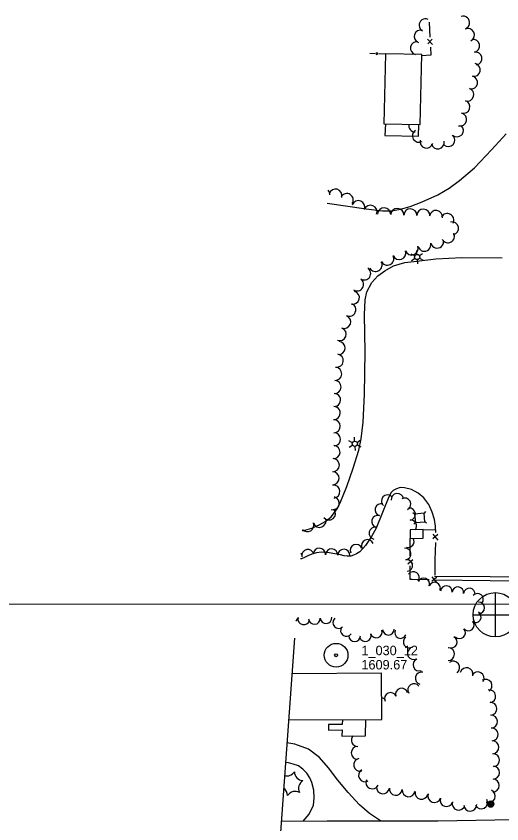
# Model space of a CAD drawing. Extents: x 189384 to 193282, y 256970 to 260388.
# Drawn here: x 190447 to 190754, y 259872 to 260383 of the extents above; entities that cross this region are included whole.
import ezdxf

# ---------------------------------------------------------------- set-up
doc = ezdxf.new("R2010")
doc.units = 0
for name, color, linetype in [('E_DWY', 7, 'Continuous'), ('E_LAND_Vegetation', 7, 'Continuous'), ('E_MAP_GridLines', 7, 'Continuous'), ('E_MAP_Limits', 7, 'Continuous'), ('E_MAP_PassPoints', 7, 'Continuous'), ('E_MISCPROP', 7, 'Continuous'), ('E_MISCPROP_HvyDash', 7, 'Continuous'), ('E_MISCPROP_HvyLine', 7, 'Continuous'), ('E_MISCPROP_Railing', 7, 'Continuous'), ('E_RDWY', 7, 'Continuous'), ('E_UTL_AboveGroundPipe', 7, 'Continuous')]:
    doc.layers.add(name, color=color, linetype=linetype)

# ---------------------------------------------------------------- blocks, each defined once
blk = doc.blocks.new('PP')
at = {"layer": 'E_MAP_PassPoints'}
for radius in [7.5, 0.96]:
    blk.add_circle((0, 0), radius, dxfattribs=at)
blk = doc.blocks.new('PHOTOC')
at = {"layer": 'E_MAP_Limits'}
for p, q in [((0.12, 14.06), (0.06, -13.8)), ((-13.79, 0.03), (14.12, 0.01))]:
    blk.add_line(p, q, dxfattribs=at)
blk.add_circle((0.17, 0.03), 14, dxfattribs=at)
blk = doc.blocks.new('POLE_1')
at = {"layer": 'E_MISCPROP'}
for radius in [2.02, 1.51, 1.01, 0.504]:
    blk.add_circle((0.03, -0.09), radius, dxfattribs=at)
blk = doc.blocks.new('PED')
at = {"layer": 'E_UTL_AboveGroundPipe'}
for p, q in [((-2.34, 2.71), (-3.29, 3.77)), ((3.06, 2.71), (4.02, 3.77)), ((-3.29, -4.35), (-2.34, -3.29)), ((4.02, -4.35), (3.06, -3.29))]:
    blk.add_line(p, q, dxfattribs=at)
blk.add_lwpolyline([(-2.34, -3.29), (3.06, -3.29), (3.06, 2.71), (-2.34, 2.71)], close=True, dxfattribs=at)
blk = doc.blocks.new('LTP')
at = {"layer": 'E_MISCPROP'}
for p, q in [((-1.61, 0.09), (-4.22, 0.17)), ((-0.78, 1.46), (-1.98, 3.76)), ((0.86, 1.37), (2.22, 3.6)), ((1.66, 0), (4.18, -0.06)), ((-0.86, -1.4), (-2.22, -3.59)), ((0.78, -1.44), (2.02, -3.62))]:
    blk.add_line(p, q, dxfattribs=at)
blk.add_circle((0.02, 0.01), 1.64, dxfattribs=at)

msp = doc.modelspace()

# ---------------------------------------------------------------- linework, layer by layer
at = {"layer": 'E_DWY'}
for points in [[(190643.16, 260264.92), (190667.89, 260261.27), (190678.21, 260260.12), (190683.78, 260260.16), (190689.54, 260261.1), (190695.61, 260262.79), (190703.32, 260265.85), (190713.11, 260270.21), (190720.22, 260274.32), (190726.8, 260279.31), (190736.3, 260287.29), (190746.97, 260298.59), (190756.41, 260308.77)], [(190627.59, 260057.72), (190633.42, 260059.47), (190638.58, 260061.64), (190642.3, 260063.74), (190645.66, 260066.61), (190649.08, 260071), (190651.49, 260075.37), (190655.58, 260085.72), (190659.68, 260097.44), (190663.3, 260108.83), (190664.72, 260115.93), (190665.9, 260126.36), (190666.8, 260144.09), (190667.19, 260171), (190666.82, 260194.34), (190667.22, 260203.75), (190668.32, 260208.94), (190671.46, 260214.83), (190675.26, 260219.05), (190679.6, 260222.23), (190685.18, 260225.38), (190692.26, 260227.29), (190699.93, 260228.32), (190711.79, 260229.61), (190728.33, 260230.48), (190753.84, 260230.25)], [(190711.73, 260058.38), (190711.64, 260060.68), (190711.1, 260064.98), (190709.66, 260069.51), (190707.39, 260074.47), (190704.29, 260078.62), (190700.73, 260081.63), (190696.51, 260083.88), (190692.13, 260084.98), (190689.38, 260085.07), (190687.06, 260084.28), (190684.98, 260083.25), (190683.75, 260082.04), (190682.18, 260079.32), (190674.24, 260059.34), (190671.19, 260054.11), (190667.38, 260048.37), (190663.85, 260044.39), (190661.64, 260043.17), (190659.83, 260042.34), (190658.07, 260041.73), (190655.9, 260041.74), (190653.92, 260041.91), (190651.61, 260042.49), (190644.37, 260043.75), (190639.61, 260044.24), (190636.46, 260043.72), (190634.19, 260043.13), (190631.39, 260042.07), (190629.25, 260040.99), (190626.93, 260040.11), (190626.25, 260039.94)], [(190711.08, 260026.64), (190746.18, 260026.36), (190775.97, 260026.01), (190799.66, 260025.72), (190848.64, 260026.04), (190882.45, 260024.72), (190913.98, 260024.45), (190936.58, 260024.1), (190955.27, 260023.64), (190967.58, 260022.95), (190981.47, 260021.68), (190988, 260020.82), (190991.83, 260019.97), (190995.29, 260017.95), (190997.01, 260015.5), (190998.22, 260011.96), (190998.94, 260008.09)], [(190711.1, 260029.14), (190746.2, 260028.86), (190776, 260028.51), (190799.66, 260028.22), (190848.68, 260028.54), (190882.51, 260027.22), (190914.01, 260026.95), (190936.63, 260026.6), (190955.37, 260026.14), (190967.76, 260025.44), (190981.75, 260024.16), (190988.44, 260023.29), (190992.75, 260022.33), (190997.03, 260019.84), (190999.26, 260016.65), (191000.65, 260012.6), (191001.4, 260008.55)], [(190677, 259874.33), (190669.93, 259878.96), (190663.6, 259884.48), (190656.41, 259892.24), (190649.97, 259900.15), (190643.94, 259907.81), (190638.28, 259914.45), (190631.41, 259919.64), (190622.87, 259922.86), (190617.74, 259923.74)], [(190628.03, 259874.16), (190631.79, 259878.62), (190634.49, 259884.23), (190634.97, 259888.79), (190634.74, 259893.77), (190633.47, 259898.57), (190632.16, 259901.63), (190630.28, 259904.55), (190627.86, 259906.94), (190625.09, 259909.11), (190621.72, 259910.26), (190618.86, 259911.08), (190616.84, 259911.19)]]:
    msp.add_lwpolyline(points, dxfattribs=at)
at = {"layer": 'E_LAND_Vegetation'}
for centre, radius, start, end in [((190729.17, 260379.09), 4.08, 289.7317, 109.7317), ((190705.27, 260377.44), 4.01, 63.7046, 243.7046), ((190702.16, 260370.36), 4.01, 71.8731, 251.8731), ((190732.21, 260371.28), 4.08, 296.8045, 116.8045), ((190735.5, 260364.44), 4.08, 280.2013, 100.2013), ((190699.78, 260362.94), 4.01, 78.7424, 258.7424), ((190698.21, 260355.08), 4.01, 78.7424, 104.5755), ((190736.95, 260356.41), 4.08, 280.2013, 100.2013), ((190735.91, 260349.15), 4.08, 258.1186, 78.1186), ((190734.23, 260341.16), 4.08, 258.1186, 78.1186), ((190731.83, 260333.56), 4.08, 252.3046, 72.3046), ((190729.35, 260325.79), 4.08, 252.3046, 72.3046), ((190727.21, 260317.82), 4.08, 255.1451, 75.1451), ((190698.81, 260314), 4.08, 169.5023, 269.5561), ((190725.19, 260310.9), 4.08, 228.1112, 48.1112), ((190701.17, 260307.51), 4.08, 120.0962, 300.0962), ((190719.75, 260304.83), 4.08, 228.1112, 48.1112), ((190705.98, 260303.79), 4.08, 164.9484, 344.9484), ((190713.04, 260303.34), 4.08, 191.5949, 11.5949), ((190640.84, 260270.27), 4.12, 359.7928, 44.5617), ((190648.48, 260269.72), 4.12, 343.9129, 163.9129), ((190655.56, 260266.88), 4.12, 327.6954, 147.6954), ((190662.92, 260262.42), 4.12, 338.9409, 158.9409), ((190670.62, 260259.45), 4.12, 338.9409, 158.9409), ((190679.23, 260257.87), 4.12, 357.3724, 177.3724), ((190687.47, 260257.5), 4.12, 357.3724, 177.3724), ((190695.76, 260257.22), 4.12, 358.7942, 178.7942), ((190704.01, 260257.04), 4.12, 358.7942, 178.7942), ((190711.95, 260256.2), 4.12, 351.6557, 171.6557), ((190719.12, 260254.22), 4.12, 331.065, 151.065), ((190722.15, 260248.98), 4.12, 283.6284, 103.6284), ((190719.58, 260244), 4.12, 208.3986, 28.3986), ((190712.66, 260240.57), 4.12, 193.8681, 13.8681), ((190688.81, 260233.35), 4.12, 200.4378, 20.4378), ((190696.54, 260236.23), 4.12, 200.4378, 20.4378), ((190704.65, 260238.6), 4.12, 193.8681, 13.8681), ((190681.19, 260229.83), 4.12, 204.903, 24.903), ((190673.78, 260225.88), 4.12, 209.5362, 29.5362), ((190666.63, 260220.46), 4.12, 237.0695, 57.0695), ((190662.14, 260213.54), 4.12, 237.0695, 57.0695), ((190659.5, 260205.13), 4.12, 255.8504, 75.8504), ((190657.22, 260197.57), 4.12, 246.2545, 66.2545), ((190653.98, 260189.85), 4.12, 249.9751, 69.9751), ((190651.16, 260182.1), 4.12, 249.9751, 69.9751), ((190650.45, 260173.35), 4.12, 266.2115, 86.2115), ((190649.33, 260165.32), 4.12, 262.11, 82.11), ((190648.26, 260156.98), 4.12, 267.0513, 87.0513), ((190647.84, 260148.74), 4.12, 267.0513, 87.0513), ((190647.55, 260140.46), 4.12, 268.3189, 88.3189), ((190647.32, 260132.21), 4.12, 268.3189, 88.3189), ((190647.36, 260123.88), 4.12, 271.1892, 91.1892), ((190647.53, 260115.63), 4.12, 271.1892, 91.1892), ((190647.23, 260107.52), 4.12, 267.2181, 87.2181), ((190646.83, 260099.24), 4.12, 268.6954, 88.6954), ((190646.64, 260090.99), 4.12, 268.6954, 88.6954), ((190647.18, 260082.57), 4.12, 274.7966, 94.7966), ((190646.75, 260075.15), 4.12, 254.1658, 74.1658), ((190681.32, 260076.52), 3.87, 47.8621, 227.8621), ((190687.55, 260077.47), 3.87, 6.589, 186.589), ((190692.17, 260074.59), 3.87, 298.2182, 118.2182), ((190644.32, 260068.71), 4.12, 219.4471, 39.4471), ((190677.34, 260071.03), 3.87, 73.7025, 253.7025), ((190695.12, 260068.26), 3.87, 276.5824, 96.5824), ((190675.17, 260063.6), 3.87, 73.7025, 253.7025), ((190630.62, 260061.31), 4.12, 223.8566, 19.3434), ((190638.4, 260064.04), 4.12, 199.3434, 19.3434), ((190695.84, 260060.74), 3.87, 323.2898, 90.8735), ((190673.54, 260056.19), 3.87, 78.1496, 258.1496), ((190668.76, 260048.28), 3.87, 22.9542, 202.9542), ((190694.43, 260050.91), 3.67, 253.3428, 33.6172), ((190694.43, 260050.91), 3.67, 69.6684, 73.3428), ((190631.03, 260042.12), 3.87, 11.0113, 191.0113), ((190638.25, 260042.83), 3.87, 357.2598, 177.2598), ((190645.99, 260042.47), 3.87, 357.777, 177.777), ((190653.72, 260042.17), 3.87, 357.777, 177.777), ((190661.63, 260045.26), 3.87, 22.9542, 202.9542), ((190692.53, 260043.1), 3.67, 277.6635, 97.6635), ((190623.96, 260040.72), 3.87, 27.6638, 48.3639), ((190693.51, 260035.82), 3.67, 277.6635, 97.6635), ((190697.7, 260028.25), 3.67, 325.1822, 145.1822), ((190704.25, 260024.19), 3.67, 338.4735, 158.4735), ((190711.07, 260021.5), 3.67, 338.3585, 158.3585), ((190718.51, 260019.23), 3.67, 354.9425, 174.9425), ((190725.78, 260018.57), 3.67, 353.7044, 173.7044), ((190733.08, 260017.77), 3.67, 353.7044, 173.7044), ((190738.2, 260014.44), 3.67, 319.6746, 139.6746), ((190739, 260008.94), 3.67, 271.5611, 91.5611), ((190736.83, 260003.29), 3.67, 237.4535, 57.4535), ((190621.2, 260003.66), 3.68, 304.87, 347.0696), ((190628.37, 260002.01), 3.68, 167.0696, 347.0696), ((190635.18, 260002.29), 3.68, 183.8188, 3.8188), ((190642.51, 260002.8), 3.68, 184.1029, 4.1029), ((190650.52, 259999.66), 3.68, 132.1083, 312.1083), ((190732.44, 259998.12), 3.67, 221.2581, 41.2581), ((190655.34, 259994.64), 3.68, 144.4256, 324.4256), ((190674.29, 259993.73), 3.68, 198.4276, 18.4276), ((190681.87, 259995.51), 3.68, 181.8143, 1.8143), ((190689.54, 259993.42), 3.68, 156.6962, 336.6962), ((190726.92, 259993.22), 3.67, 222.5971, 42.5971), ((190660.52, 259991.32), 3.68, 180.3135, 0.3135), ((190667.32, 259991.41), 3.68, 198.4276, 18.4276), ((190694.96, 259987.4), 3.68, 124.5211, 304.5211), ((190721.7, 259987.33), 3.67, 243.8072, 63.8072), ((190697.79, 259980.2), 3.86, 119.7369, 299.7216), ((190719.62, 259979.74), 4.06, 269.5468, 89.5315), ((190701.31, 259972.99), 3.86, 110.6547, 290.6394), ((190722.84, 259971.27), 4.06, 306.5246, 126.5092), ((190731.25, 259967.13), 4.06, 344.1424, 164.1271), ((190702.74, 259964.49), 3.86, 76.3972, 256.3819), ((190738.3, 259964.46), 4.06, 329.9333, 149.9179), ((190698.03, 259957.23), 3.86, 34.5735, 214.5582), ((190743.33, 259959.78), 4.06, 302.3423, 122.3269), ((190683.32, 259951.58), 3.86, 23.2719, 203.2566), ((190690.25, 259954.3), 3.86, 15.45, 195.4347), ((190745.61, 259953.08), 4.06, 278.411, 98.3957), ((190676.91, 259948.36), 3.86, 37.4061, 78.0855), ((190746.38, 259945.22), 4.06, 272.6627, 92.6474), ((190746.76, 259937.1), 4.06, 272.6627, 92.6474), ((190747.16, 259928.96), 4.06, 273.3562, 93.3409), ((190662.57, 259925.43), 4.06, 139.7405, 269.6971), ((190747.64, 259920.85), 4.06, 273.3562, 93.3409), ((190662.53, 259917.3), 4.06, 89.7124, 269.6971), ((190664, 259909.79), 4.06, 102.0578, 282.0425), ((190748.11, 259912.74), 4.06, 273.3562, 93.3409), ((190748.14, 259904.81), 4.06, 268.4924, 88.4771), ((190617.67, 259908.47), 5.72, 255.6394, 327.0092), ((190628.19, 259905.48), 5.72, 181.2443, 267.0092), ((190667.1, 259903.1), 4.06, 119.9954, 299.9801), ((190630.86, 259894.87), 5.72, 121.2443, 207.0092), ((190671.75, 259898.56), 4.06, 154.473, 334.4577), ((190747.93, 259896.69), 4.06, 268.4924, 88.4771), ((190612.48, 259890.24), 5.72, 1.2443, 56.079), ((190623.01, 259887.25), 5.72, 61.2443, 147.0092), ((190678.48, 259895.5), 4.06, 173.4389, 353.4235), ((190686.55, 259894.57), 4.06, 173.4389, 353.4235), ((190694.62, 259893.64), 4.06, 173.4389, 353.4235), ((190702.78, 259892.03), 4.06, 168.134, 348.1187), ((190745.4, 259889.94), 4.06, 246.0176, 66.0023), ((190710.91, 259890), 4.06, 161.0837, 341.0684), ((190718.59, 259887.37), 4.06, 161.0837, 341.0684), ((190740.5, 259886.02), 4.06, 206.6366, 26.6213), ((190726.29, 259885.21), 4.06, 164.6061, 344.5908), ((190733.63, 259884.48), 4.06, 182.2339, 2.2186)]:
    msp.add_arc(centre, radius, start, end, dxfattribs=at)
at = {"layer": 'E_MAP_GridLines'}
msp.add_line((190145.98, 260011.08), (191645.98, 260012.15), dxfattribs=at)
msp.add_line((190145.98, 260011.08), (191645.98, 260012.15), dxfattribs=at)
at = {"layer": 'E_MAP_Limits'}
msp.add_lwpolyline([(190622.49, 259989.85), (190597.72, 259644.89), (190538.23, 259147.8)], dxfattribs=at)
at = {"layer": 'E_MISCPROP_HvyDash'}
for points in [[(190680.04, 260315.09), (190679.61, 260307.78), (190700.87, 260307.35), (190701.15, 260314.59)], [(190652.82, 259938.36), (190652.69, 259935.24), (190644.08, 259935.3), (190643.94, 259931.75), (190652.67, 259931.87), (190652.52, 259927.97), (190667.53, 259928.15), (190667.58, 259938.42)]]:
    msp.add_lwpolyline(points, dxfattribs=at)
at = {"layer": 'E_MISCPROP_HvyLine'}
for points in [[(190680.1, 260359.36), (190679.07, 260315.11), (190679.07, 260315.11), (190701.98, 260314.57), (190703.01, 260358.82), (190703.01, 260358.82), (190703.01, 260358.82)], [(190695.74, 260052.9), (190703.91, 260053.08), (190703.79, 260058.53), (190703.79, 260058.53), (190703.79, 260058.53), (190695.62, 260058.35)]]:
    msp.add_lwpolyline(points, close=True, dxfattribs=at)
msp.add_lwpolyline([(190618.78, 259938.22), (190677.76, 259938.46), (190677.76, 259938.46), (190677.64, 259967.62), (190620.88, 259967.38)], dxfattribs=at)
at = {"layer": 'E_MISCPROP_Railing'}
for p, q in [((190706.52, 260368.61), (190709.81, 260365.22)), ((190709.63, 260368.61), (190706.74, 260365.77)), ((190674.15, 260358.95), (190675.51, 260360.05)), ((190674.25, 260360.1), (190675.2, 260358.94)), ((190709.99, 260055.57), (190713.05, 260051.9)), ((190713.12, 260055.34), (190709.99, 260052.69)), ((190694.23, 260036.83), (190697.31, 260039.54)), ((190697.37, 260036.66), (190694.24, 260040.27)), ((190709.43, 260028.56), (190712.5, 260024.89)), ((190712.57, 260028.33), (190709.44, 260025.68))]:
    msp.add_line(p, q, dxfattribs=at)
for points in [[(190707.6, 260379.33), (190708.12, 260369.81)], [(190708.47, 260363.51), (190708.75, 260358.44), (190703, 260358.07)], [(190670.23, 260359.7), (190673.76, 260359.58)], [(190676.09, 260359.5), (190680.1, 260359.36)], [(190703.79, 260058.53), (190711.73, 260058.38), (190711.7, 260056.66)], [(190695.7, 260041.92), (190695.74, 260052.9)], [(190711.57, 260050.28), (190711.34, 260039.3)], [(190711.34, 260039.3), (190711.14, 260029.65)], [(190696.73, 260026.94), (190695.65, 260026.97), (190695.68, 260035.54)], [(190707.71, 260026.71), (190696.73, 260026.94)]]:
    msp.add_lwpolyline(points, dxfattribs=at)
at = {"layer": 'E_RDWY'}
msp.add_lwpolyline([(190614.18, 259874.08), (190643.27, 259874.25), (190673.64, 259874.33), (190713.05, 259874.38), (190749.1, 259874.89), (190784.75, 259875.49), (190803.44, 259875.58), (190834.79, 259876.88), (190868.89, 259877.7), (190910.69, 259879.44), (190934.84, 259880.17), (190958.89, 259883.07), (190971.15, 259885.9), (190978.41, 259888.91), (190984.49, 259892.96)], dxfattribs=at)

# ---------------------------------------------------------------- block references
at = {"layer": 'E_MAP_Limits', "rotation": 0.04071536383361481}
msp.add_blockref('PHOTOC', (190749.31, 260004.65), dxfattribs=at)
msp.add_blockref('PHOTOC', (190749.31, 260004.65), dxfattribs=at)
at = {"layer": 'E_MAP_PassPoints', "rotation": 0.04071715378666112}
msp.add_blockref('PP', (190648.84, 259979.04), dxfattribs=at)
msp.add_blockref('PP', (190648.84, 259979.04), dxfattribs=at)
at = {"layer": 'E_MISCPROP'}
for name, p, xscale, yscale, rotation in [('LTP', (190700.1, 260230.82), 1.0000018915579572, 1.0000018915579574, 95.09922305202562), ('LTP', (190660.72, 260112.73), 1.0000018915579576, 1.0000018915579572, 95.09922374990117), ('POLE_1', (190746.46, 259884.91), 1.000001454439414, 1.000001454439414, 86.2723228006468)]:
    msp.add_blockref(name, p, dxfattribs=dict(at, xscale=xscale, yscale=yscale, rotation=rotation))
at = {"layer": 'E_UTL_AboveGroundPipe', "xscale": 1.0000018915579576, "yscale": 1.0000018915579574, "rotation": 95.09922302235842}
msp.add_blockref('PED', (190701.44, 260065.46), dxfattribs=at)

# ---------------------------------------------------------------- texts
at = {"layer": 'E_MAP_PassPoints'}
for s, p in [('1_030_12', (190664.84, 259979.05)), ('1_030_12', (190664.84, 259979.05)), ('1609.67', (190664.85, 259970.05)), ('1609.67', (190664.85, 259970.05))]:
    msp.add_text(s, height=6, rotation=0.0407, dxfattribs=at).set_placement(p)

doc.saveas('drawing.dxf')
